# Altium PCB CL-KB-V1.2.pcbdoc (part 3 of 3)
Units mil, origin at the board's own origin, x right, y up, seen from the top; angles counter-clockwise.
Board outline 3269.95 x 5989.25 mil, 2 copper layers (Top Layer, Bottom Layer); 76 components, 86 nets, 398 pads, 855 vias.
Unrouted connection lines stored in the file: 1.
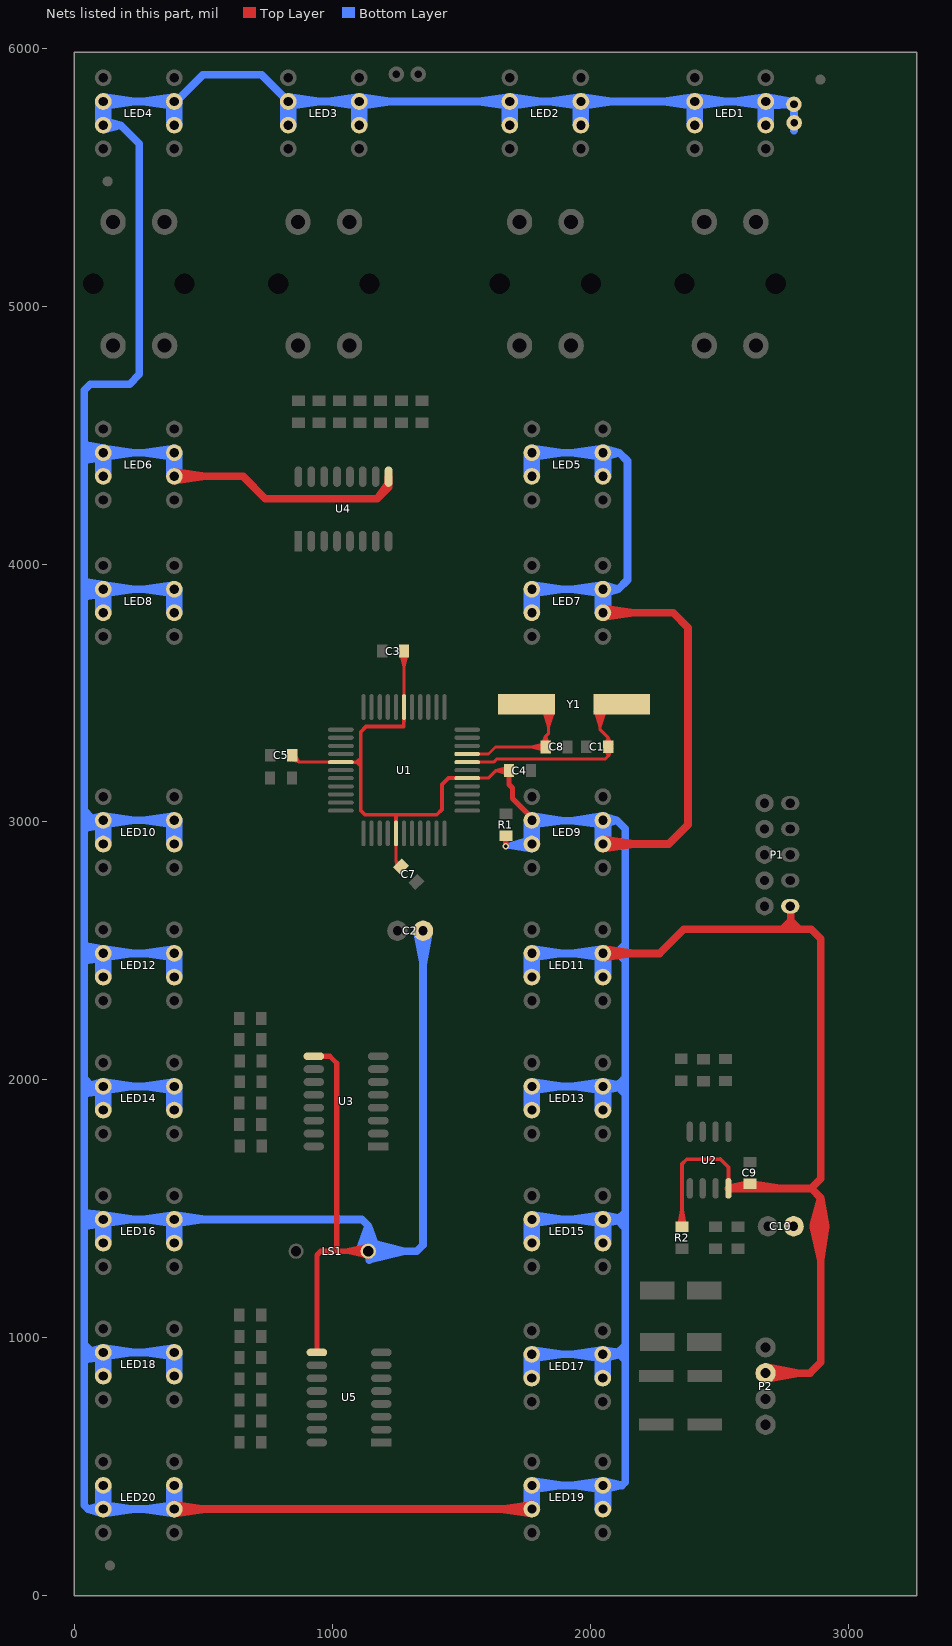
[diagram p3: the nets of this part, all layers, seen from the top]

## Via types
v1: diameter 25, hole 15, Top Layer to Bottom Layer, tented both sides, 855 vias

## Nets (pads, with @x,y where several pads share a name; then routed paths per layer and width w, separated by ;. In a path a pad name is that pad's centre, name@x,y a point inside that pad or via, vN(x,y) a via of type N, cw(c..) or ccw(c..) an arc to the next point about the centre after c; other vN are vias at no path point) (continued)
VCC: C2.1 C3.2 C4.2 C5.1 C7.2 C9.1 C10.1 LED1.A LED2.A LED3.A LED4.A LED5.A LED6.A LED7.A LED8.A LED9.A LED10.A LED11.A LED12.A LED13.A LED14.A LED15.A LED16.A LED17.A LED18.A LED19.A LED20.A LS1.1 P1.2 P2.2 pad.3 pad.4 R1.2 R2.1 U1.5 U1.17 U1.27 U1.38 U2.8 U3.9 U4.9 U5.9 | length 103418.5
  Top Layer w12: C5.1@836.52,3241.59 870,3232 ; C5.1@843,3254 870,3232 ; C5.1@843,3259 870,3232 ; C5.1@853.84,3262.85 870,3232 ; 946,3232 U1.27@990,3232 ; U1.27@1032,3232 870,3232 ; 1246,2870 U1.38@1246,2914 ; U1.38@1246,2956 1246,2846 ; C7.2@1252.81,2820.08 1246,2846 ; C3.2@1263.11,3656.25 1277,3602 ; C7.2@1271.92,2839.19 1246,2846 ; U1.17@1277,3446 C3.2@1277,3663 ; U1.17@1277,3488 1277,3532 ; C3.2@1277,3658 1277,3602 ; C3.2@1290.89,3656.25 1277,3602 ; U1.5@1522,3170 1603.68,3170 ; U1.5@1564,3170 1603.68,3170 ; C4.2@1682.61,3185.13 1632.68,3199 ; C4.2@1682.61,3212.87 1632.68,3199 ; 1246,2846 C7.2@1264.95,2827.05 1246,2846 ; 1603.68,3170 1632.68,3199 ; 1632.68,3199 C4.2@1684.5,3199 1632.68,3199
  Top Layer w15: U1.27@1032,3232 1108,3232 U1.27@1074,3232 ; 1094,3232 1103,3241 ; 1095,3232 1104,3223 ; U1.38@1246,2956 1246,3028 ; U1.38@1246,2998 1246,3028 ; U1.17@1276,3413 1276,3370 ; U1.17@1277,3404 1276,3370 ; U1.5@1480,3170 1449,3170 ; U1.5@1522,3170 1449,3170 ; R2.1@2343.56,1430.2 2356,1494 R2.1@2368.44,1430.2 ; R2.1@2356,1429 2356,1673 2374,1691 2505,1691 ; 2504,1692 2536,1660 ; U2.8@2536,1578 2536,1660 ; U2.8@2536,1606 2536,1660 ; 1246,3028 1404,3028 1424,3048 1424,3145 1449,3170 ; 1246,3028 1126,3028 1109,3045 1109,3349 1130,3370 1276,3370
  Top Layer w20: U3.9@927,2091 989,2091 ; U5.9@938.98,941.73 938.98,1320.02 953.28,1334.33 LS1.1@1138.26,1334.33 1048.73,1334.33 ; U3.9@952,2091 989,2091 ; 1016,1334.33 1016,2064 989,2091 ; LS1.1@1136.13,1314.92 1048.73,1334.33 ; LS1.1@1136.13,1353.74 1048.73,1334.33 ; C4.2@1684.5,3194 1684.5,3145.27 ; C4.2@1684.5,3199 1684.5,3145.27 ; LED9.A@1773.2,3006.17 1773.2,3015.8 1698,3091 1698,3131.77 1684.5,3145.27 ; v1(1672,2906) R1.2@1672,2947 v1(1672,2906)
  Top Layer w30: LED20.A@385.8,333.6 LED19.A@1773.2,333.6 1650.7,333.6 ; LED6.A@385.8,4341.08 651.92,4341.08 739,4254 1172,4254 ; LED20.A@387.05,316.14 508.3,333.6 LED20.A@387.05,351.05 ; LED6.A@387.05,4323.62 508.3,4341.08 LED6.A@387.05,4358.53 ; U4.9@1217,4340 1217,4299 ; LED19.A@1771.95,316.14 1650.7,333.6 ; LED19.A@1771.95,351.05 1650.7,333.6 ; LED11.A@2048.79,2490.03 2269.03,2490.03 2363,2584 2745,2584 ; LED9.A@2048.79,2914.3 2304.3,2914.3 2379,2989 2379,3754 2321.45,3811.55 LED7.A@2048.79,3811.55 ; LED11.A@2050.04,2472.57 2171.29,2490.03 LED11.A@2050.04,2507.48 ; LED9.A@2050.04,2896.85 2171.29,2914.3 LED9.A@2050.04,2931.76 ; LED7.A@2050.04,3794.09 2171.29,3811.55 LED7.A@2050.04,3829 ; C9.1@2614,1595.5 U2.8@2536,1578 2857,1578 ; C9.1@2624,1595.5 2738.5,1578 ; P2.2@2680,861 2852,861 2894,903 2894,1541 ; P2.2@2682.3,836.74 2809.37,861 P2.2@2682.3,885.26 ; 2822,2584 2811,2584 ; 2864.84,1427.78 2894,1301.36 ; 2864.93,1434.79 2894,1541 ; 2913.33,1429.65 2894,1301.36 ; 2913.32,1432.59 2894,1541 ; 1172,4254 1217,4299 ; 1172,4254 U4.9@1217,4315 ; 1217,4299 U4.9@1217,4315 ; 1217,4299 U4.9@1217,4315 ; 2745,2584 2778,2617 ; 2745,2584 2778,2584 ; 2778,2584 2778,2617 ; 2778,2584 2811,2584 ; 2778,2617 2778,2671 P1.2@2776,2673 2778,2617 ; 2778,2617 2811,2584 ; 2811,2584 2857,2584 2894,2547 2894,1615 2857,1578 ; 2857,1578 2894,1541 ; 2894,1301.36 2889,1431 2894,1541
  Bottom Layer w20: 1742.42,2927.37 v1(1672,2906) ; 1744.09,2896.17 v1(1672,2906) ; LED9.A@1744.36,2911.73 v1(1672,2906) ; LED9.A@1768.52,2936.31 v1@1680.05,2906 ; LED9.A@1772.48,2891.82 v1@1680.05,2906 ; v1(1672,2906) 1764.89,2906 LED9.A@1773.2,2914.3 v1@1680.05,2906
  Bottom Layer w30: 37,2004 61,1979 ; 37,3043 61,3018 ; 38,971 62,946 ; LED20.A@92.78,331.93 LED20.A@92.78,423.79 ; LED18.A@92.78,848.07 LED18.A@92.78,939.93 ; LED16.A@92.78,1364.21 LED16.A@92.78,1456.08 ; LED14.A@92.78,1880.35 LED14.A@92.78,1972.22 ; LED12.A@92.78,2396.5 LED12.A@92.78,2488.36 ; LED10.A@92.78,2912.64 LED10.A@92.78,3004.5 ; LED8.A@92.78,3809.88 LED8.A@92.78,3901.74 ; LED6.A@92.78,4339.41 LED6.A@92.78,4431.27 ; LED4.A@92.78,5702.4 LED4.A@92.78,5794.26 ; LED20.A@93.42,338.54 LED20.A@127.62,423.79 ; LED18.A@93.42,854.68 LED18.A@127.62,939.93 ; LED16.A@93.42,1370.82 LED16.A@127.62,1456.08 ; LED14.A@93.42,1886.96 LED14.A@127.62,1972.22 ; LED12.A@93.42,2403.1 LED12.A@127.62,2488.36 ; LED10.A@93.42,2919.24 LED10.A@127.62,3004.5 ; LED8.A@93.42,3816.49 LED8.A@127.62,3901.74 ; LED6.A@93.42,4346.02 LED6.A@127.62,4431.27 ; LED4.A@93.42,5709.01 LED4.A@127.62,5794.26 ; LED6.A@101.31,4417.86 42,4463 ; LED12.A@101.43,2474.88 41,2520 ; LED6.A@101.51,4448.13 42,4404 ; LED10.A@101.6,3021.4 39,2976 ; LED12.A@101.68,2505.31 42,2462 ; LED8.A@101.66,3888.14 43,3931 ; LED14.A@101.82,1989.25 39,1945 ; LED8.A@102,3918.87 38,3875 ; LED18.A@102.05,957.09 39,914 ; LED16.A@102.11,1442.23 41,1484 ; LED16.A@102.11,1473.26 40,1431 ; LED10.A@104.67,3022.77 64,3000 ; LED6.A@104.76,4449.57 67,4428 ; LED6.A@104.83,4416.28 66,4438 ; LED12.A@104.98,2473.32 65,2495 ; LED14.A@105.12,1990.63 64,1969 ; LED12.A@105.1,2506.76 67,2486 ; LED8.A@105.39,3920.24 63,3899 ; LED18.A@105.57,958.48 64,938 ; LED8.A@105.65,3886.51 67,3906 ; LED16.A@105.79,1474.68 65,1455 ; LED16.A@106.34,1440.67 65,1459 ; LED16.A@107.3,1475 65,1459 ; LED6.A@107.38,4415.67 56.06,4432.94 ; LED6.A@107.38,4450.21 56.06,4432.94 ; LED20.A@107.62,316.29 50.9,333.6 ; LED20.A@107.62,350.9 50.9,333.6 ; LED8.A@107.7,3920.73 67,3906 ; LED18.A@107.8,924.27 46.6,941.6 ; LED18.A@107.8,958.93 46.6,941.6 ; LED16.A@107.87,1440.4 65,1455 ; LED14.A@107.86,1956.54 44.88,1973.88 ; LED14.A@107.86,1991.23 44.88,1973.88 ; LED12.A@107.96,2472.67 42.03,2490.03 ; LED12.A@107.96,2507.38 42.03,2490.03 ; LED10.A@108.09,2988.8 37.83,3006.17 ; LED10.A@108.09,3023.54 37.83,3006.17 ; LED8.A@108.07,3886.04 38.41,3903.41 ; LED8.A@108.07,3920.78 38.41,3903.41 ; LED16.A@108.13,1440.37 36.26,1457.74 ; LED16.A@108.13,1475.12 36.26,1457.74 ; LED18.A@108.25,924.21 64,938 ; LED12.A@108.28,2472.63 67,2486 ; LED8.A@108.59,3885.99 63,3899 ; LED6.A@108.65,4415.51 67,4428 ; LED14.A@108.73,1956.45 64,1969 ; LED12.A@108.74,2507.46 65,2495 ; LED6.A@108.74,4450.38 66,4438 ; LED10.A@109.22,2988.69 64,3000 ; LED20.A@111.45,316.14 232.7,333.6 LED20.A@111.45,351.05 ; LED18.A@111.45,924.15 232.7,941.6 LED18.A@111.45,959.06 ; LED16.A@111.45,1440.29 232.7,1457.74 LED16.A@111.45,1475.2 ; LED14.A@111.45,1956.43 232.7,1973.88 LED14.A@111.45,1991.34 ; LED12.A@111.45,2472.57 232.7,2490.03 LED12.A@111.45,2507.48 ; LED10.A@111.45,2988.71 232.7,3006.17 LED10.A@111.45,3023.62 ; LED8.A@111.45,3885.96 232.7,3903.41 LED8.A@111.45,3920.87 ; LED6.A@111.45,4415.48 232.7,4432.94 LED6.A@111.45,4450.39 ; LED4.A@111.45,5778.48 232.7,5795.93 LED4.A@111.45,5813.39 ; LED4.A@112.46,5686.71 177.93,5704.07 ; LED4.A@112.46,5721.42 177.93,5704.07 ; LED16.A@114.43,1474.72 41,1484 ; LED16.A@114.49,1440.77 40,1431 ; LED18.A@114.62,924.67 39,914 ; LED8.A@114.73,3886.51 38,3875 ; LED12.A@114.89,2473.16 42,2462 ; LED8.A@114.85,3920.28 43,3931 ; LED14.A@114.89,1957.02 39,1945 ; LED6.A@115.09,4416.13 42,4404 ; LED10.A@115.16,2989.38 39,2976 ; LED12.A@115.25,2506.78 41,2520 ; LED6.A@115.33,4449.67 42,4463 ; LED20.A@126.99,338.54 LED20.A@92.78,423.79 ; LED18.A@126.99,854.68 LED18.A@92.78,939.93 ; LED16.A@126.99,1370.82 LED16.A@92.78,1456.08 ; LED14.A@126.99,1886.96 LED14.A@92.78,1972.22 ; LED12.A@126.99,2403.1 LED12.A@92.78,2488.36 ; LED10.A@126.99,2919.24 LED10.A@92.78,3004.5 ; LED8.A@126.99,3816.49 LED8.A@92.78,3901.74 ; LED6.A@126.99,4346.02 LED6.A@92.78,4431.27 ; LED4.A@126.99,5709.01 LED4.A@92.78,5794.26 ; LED20.A@127.62,331.93 LED20.A@127.62,423.79 ; LED18.A@127.62,848.07 LED18.A@127.62,939.93 ; LED16.A@127.62,1364.21 LED16.A@127.62,1456.08 ; LED14.A@127.62,1880.35 LED14.A@127.62,1972.22 ; LED12.A@127.62,2396.5 LED12.A@127.62,2488.36 ; LED10.A@127.62,2912.64 LED10.A@127.62,3004.5 ; LED8.A@127.62,3809.88 LED8.A@127.62,3901.74 ; LED6.A@127.62,4339.41 LED6.A@127.62,4431.27 ; LED4.A@127.62,5702.4 LED4.A@127.62,5794.26 ; LED20.A@368.38,423.79 LED20.A@385.8,333.6 ; LED20.A@368.38,427.13 LED20.A@368.38,335.26 ; LED18.A@368.38,939.93 LED18.A@385.8,849.74 ; LED18.A@368.38,943.27 LED18.A@368.38,851.4 ; LED16.A@368.38,1456.08 LED16.A@385.8,1365.88 ; LED16.A@368.38,1459.41 LED16.A@368.38,1367.55 ; LED14.A@368.38,1972.22 LED14.A@385.8,1882.02 ; LED14.A@368.38,1975.55 LED14.A@368.38,1883.69 ; LED12.A@368.38,2488.36 LED12.A@385.8,2398.16 ; LED12.A@368.38,2491.69 LED12.A@368.38,2399.83 ; LED10.A@368.38,3004.5 LED10.A@385.8,2914.3 ; LED10.A@368.38,3007.83 LED10.A@368.38,2915.97 ; LED8.A@368.38,3901.74 LED8.A@385.8,3811.55 ; LED8.A@368.38,3905.08 LED8.A@368.38,3813.22 ; LED6.A@368.38,4431.27 LED6.A@385.8,4341.08 ; LED6.A@368.38,4434.61 LED6.A@368.38,4342.74 ; LED4.A@368.38,5794.26 LED4.A@385.8,5704.07 ; LED4.A@368.38,5797.6 LED4.A@368.38,5705.73 ; LED20.A@369.01,420.52 LED20.A@403.22,335.26 ; LED18.A@369.01,936.66 LED18.A@403.22,851.4 ; LED16.A@369.01,1452.8 LED16.A@403.22,1367.55 ; LED14.A@369.01,1968.94 LED14.A@403.22,1883.69 ; LED12.A@369.01,2485.09 LED12.A@403.22,2399.83 ; LED10.A@369.01,3001.23 LED10.A@403.22,2915.97 ; LED8.A@369.01,3898.47 LED8.A@403.22,3813.22 ; LED6.A@369.01,4428 LED6.A@403.22,4342.74 ; LED4.A@369.01,5790.99 LED4.A@403.22,5705.73 ; LED20.A@384.55,316.14 263.3,333.6 ; LED20.A@384.55,351.05 263.3,333.6 ; LED18.A@384.55,924.15 263.3,941.6 ; LED18.A@384.55,959.06 263.3,941.6 ; LED16.A@384.55,1440.29 263.3,1457.74 ; LED16.A@384.55,1475.2 263.3,1457.74 ; LED14.A@384.55,1956.43 263.3,1973.88 ; LED14.A@384.55,1991.34 263.3,1973.88 ; LED12.A@384.55,2472.57 263.3,2490.03 ; LED12.A@384.55,2507.48 263.3,2490.03 ; LED10.A@384.55,2988.71 263.3,3006.17 ; LED10.A@384.55,3023.62 263.3,3006.17 ; LED8.A@384.55,3885.96 263.3,3903.41 ; LED8.A@384.55,3920.87 263.3,3903.41 ; LED6.A@384.55,4415.48 263.3,4432.94 ; LED6.A@384.55,4450.39 263.3,4432.94 ; LED4.A@384.55,5778.48 263.3,5795.93 ; LED4.A@384.55,5813.39 263.3,5795.93 ; LED16.A@387.05,1440.29 508.3,1457.74 LED16.A@387.05,1475.2 ; LED20.A@402.58,420.52 LED20.A@368.38,335.26 ; LED18.A@402.58,936.66 LED18.A@368.38,851.4 ; LED16.A@402.58,1452.8 LED16.A@368.38,1367.55 ; LED14.A@402.58,1968.94 LED14.A@368.38,1883.69 ; LED12.A@402.58,2485.09 LED12.A@368.38,2399.83 ; LED10.A@402.58,3001.23 LED10.A@368.38,2915.97 ; LED8.A@402.58,3898.47 LED8.A@368.38,3813.22 ; LED6.A@402.58,4428 LED6.A@368.38,4342.74 ; LED4.A@402.58,5790.99 LED4.A@368.38,5705.73 ; LED20.A@403.22,423.79 LED20.A@385.8,333.6 ; LED20.A@403.22,427.13 LED20.A@403.22,335.26 ; LED18.A@403.22,939.93 LED18.A@385.8,849.74 ; LED18.A@403.22,943.27 LED18.A@403.22,851.4 ; LED16.A@403.22,1456.08 LED16.A@385.8,1365.88 ; LED16.A@403.22,1459.41 LED16.A@403.22,1367.55 ; LED14.A@403.22,1972.22 LED14.A@385.8,1882.02 ; LED14.A@403.22,1975.55 LED14.A@403.22,1883.69 ; LED12.A@403.22,2488.36 LED12.A@385.8,2398.16 ; LED12.A@403.22,2491.69 LED12.A@403.22,2399.83 ; LED10.A@403.22,3004.5 LED10.A@385.8,2914.3 ; LED10.A@403.22,3007.83 LED10.A@403.22,2915.97 ; LED8.A@403.22,3901.74 LED8.A@385.8,3811.55 ; LED8.A@403.22,3905.08 LED8.A@403.22,3813.22 ; LED6.A@403.22,4431.27 LED6.A@385.8,4341.08 ; LED6.A@403.22,4434.61 LED6.A@403.22,4342.74 ; LED4.A@403.22,5794.26 LED4.A@385.8,5704.07 ; LED4.A@403.22,5797.6 LED4.A@403.22,5705.73 ; LED3.A@810.5,5702.4 LED3.A@810.5,5794.26 ; LED3.A@811.13,5709.01 LED3.A@845.34,5794.26 ; LED3.A@829.17,5778.48 950.42,5795.93 LED3.A@829.17,5813.39 ; LED3.A@844.71,5709.01 LED3.A@810.5,5794.26 ; LED3.A@845.34,5702.4 LED3.A@845.34,5794.26 ; LED3.A@1086.09,5794.26 LED3.A@1103.51,5704.07 ; LED3.A@1086.09,5797.6 LED3.A@1086.09,5705.73 ; LED3.A@1086.72,5790.99 LED3.A@1120.93,5705.73 ; LED3.A@1102.26,5778.48 981.01,5795.93 LED3.A@1102.26,5813.39 ; LS1.1@1104.57,1340.28 1138.26,1432.74 ; LED3.A@1104.76,5778.48 1226.01,5795.93 LED3.A@1104.76,5813.39 ; LED3.A@1120.3,5790.99 LED3.A@1086.09,5705.73 ; LED3.A@1120.93,5794.26 LED3.A@1103.51,5704.07 ; LED3.A@1120.93,5797.6 LED3.A@1120.93,5705.73 ; LS1.1@1142.46,1300.38 1277.47,1334.33 LS1.1@1142.46,1368.28 ; LS1.1@1171.95,1340.28 1138.26,1432.74 ; C2.1@1326.74,2575.7 1351,2448.63 ; C2.1@1375.26,2575.7 1351,2448.63 ; LED2.A@1670.34,5702.4 LED2.A@1670.34,5794.26 ; LED2.A@1670.97,5709.01 LED2.A@1705.18,5794.26 ; LED2.A@1686.51,5778.48 1565.26,5795.93 LED2.A@1686.51,5813.39 ; LED2.A@1689.01,5778.48 1810.26,5795.93 LED2.A@1689.01,5813.39 ; LED2.A@1704.55,5709.01 LED2.A@1670.34,5794.26 ; LED2.A@1705.18,5702.4 LED2.A@1705.18,5794.26 ; LED17.A@1754.78,932.26 LED17.A@1772.2,842.07 ; LED17.A@1754.78,935.6 LED17.A@1754.78,843.73 ; LED17.A@1755.42,928.99 LED17.A@1789.62,843.73 ; LED19.A@1755.78,423.79 LED19.A@1773.2,333.6 ; LED19.A@1755.78,427.13 LED19.A@1755.78,335.26 ; LED15.A@1755.78,1456.08 LED15.A@1773.2,1365.88 ; LED15.A@1755.78,1459.41 LED15.A@1755.78,1367.55 ; LED13.A@1755.78,1972.22 LED13.A@1773.2,1882.02 ; LED13.A@1755.78,1975.55 LED13.A@1755.78,1883.69 ; LED11.A@1755.78,2488.36 LED11.A@1773.2,2398.16 ; LED11.A@1755.78,2491.69 LED11.A@1755.78,2399.83 ; LED9.A@1755.78,3004.5 LED9.A@1773.2,2914.3 ; LED9.A@1755.78,3007.83 LED9.A@1755.76,2915.76 ; LED7.A@1755.78,3901.74 LED7.A@1773.2,3811.55 ; LED7.A@1755.78,3905.08 LED7.A@1755.78,3813.22 ; LED5.A@1755.78,4431.27 LED5.A@1773.2,4341.08 ; LED5.A@1755.78,4434.61 LED5.A@1755.78,4342.74 ; LED9.A@1755.8,3004.31 LED9.A@1772,2935 ; LED19.A@1756.41,420.52 LED19.A@1790.62,335.26 ; LED15.A@1756.41,1452.8 LED15.A@1790.62,1367.55 ; LED13.A@1756.41,1968.94 LED13.A@1790.62,1883.69 ; LED11.A@1756.41,2485.09 LED11.A@1790.62,2399.83 ; LED9.A@1756.41,3001.22 LED9.A@1790.59,2916.22 ; LED7.A@1756.41,3898.47 LED7.A@1790.62,3813.22 ; LED5.A@1756.41,4428 LED5.A@1790.62,4342.74 ; LED17.A@1773.45,916.48 1894.7,933.93 LED17.A@1773.45,951.39 ; LED9.A@1774.28,2988.7 1895.71,3004.97 ; LED19.A@1774.45,408 1895.7,425.46 LED19.A@1774.45,442.91 ; LED15.A@1774.45,1440.29 1895.7,1457.74 LED15.A@1774.45,1475.2 ; LED13.A@1774.45,1956.43 1895.7,1973.88 LED13.A@1774.45,1991.34 ; LED11.A@1774.45,2472.57 1895.7,2490.03 LED11.A@1774.45,2507.48 ; LED7.A@1774.45,3885.96 1895.7,3903.41 LED7.A@1774.45,3920.87 ; LED5.A@1774.45,4415.48 1895.7,4432.94 LED5.A@1774.45,4450.39 ; LED9.A@1774.62,3023.61 1895.71,3004.97 ; LED17.A@1788.99,928.99 LED17.A@1754.78,843.73 ; LED17.A@1789.62,932.26 LED17.A@1772.2,842.07 ; LED17.A@1789.62,935.6 LED17.A@1789.62,843.73 ; LED19.A@1789.98,420.52 LED19.A@1755.78,335.26 ; LED15.A@1789.98,1452.8 LED15.A@1755.78,1367.55 ; LED13.A@1789.98,1968.94 LED13.A@1755.78,1883.69 ; LED11.A@1789.98,2485.09 LED11.A@1755.78,2399.83 ; LED9.A@1789.99,3001.23 LED9.A@1755.76,2915.76 ; LED7.A@1789.98,3898.47 LED7.A@1755.78,3813.22 ; LED5.A@1789.98,4428 LED5.A@1755.78,4342.74 ; LED9.A@1790.52,3003.72 LED9.A@1772,2935 ; LED19.A@1790.62,423.79 LED19.A@1773.2,333.6 ; LED19.A@1790.62,427.13 LED19.A@1790.62,335.26 ; LED15.A@1790.62,1456.08 LED15.A@1773.2,1365.88 ; LED15.A@1790.62,1459.41 LED15.A@1790.62,1367.55 ; LED13.A@1790.62,1972.22 LED13.A@1773.2,1882.02 ; LED13.A@1790.62,1975.55 LED13.A@1790.62,1883.69 ; LED11.A@1790.62,2488.36 LED11.A@1773.2,2398.16 ; LED11.A@1790.62,2491.69 LED11.A@1790.62,2399.83 ; LED9.A@1790.62,3004.5 LED9.A@1773.2,2914.3 ; LED9.A@1790.62,3007.83 LED9.A@1790.59,2916.22 ; LED7.A@1790.62,3901.74 LED7.A@1773.2,3811.55 ; LED7.A@1790.62,3905.08 LED7.A@1790.62,3813.22 ; LED5.A@1790.62,4431.27 LED5.A@1773.2,4341.08 ; LED5.A@1790.62,4434.61 LED5.A@1790.62,4342.74 ; LED2.A@1945.93,5794.26 LED2.A@1963.35,5704.07 ; LED2.A@1945.92,5794.38 LED2.A@1963.35,5697.35 ; LED2.A@1945.93,5797.6 LED2.A@1945.93,5705.73 ; LED2.A@1946.57,5790.99 LED2.A@1980.78,5705.73 ; LED2.A@1962.1,5778.48 1840.85,5795.93 LED2.A@1962.1,5813.39 ; LED2.A@1964.6,5778.48 2085.85,5795.93 LED2.A@1964.6,5813.39 ; LED2.A@1980.14,5790.99 LED2.A@1945.93,5705.73 ; LED2.A@1980.78,5794.26 LED2.A@1963.35,5704.07 ; LED2.A@1980.79,5794.38 LED2.A@1963.35,5697.35 ; LED2.A@1980.78,5797.6 LED2.A@1980.78,5705.73 ; LED17.A@2030.38,840.4 LED17.A@2030.38,932.26 ; LED17.A@2031.01,847.01 LED17.A@2065.22,932.26 ; LED19.A@2031.37,331.93 LED19.A@2031.37,423.79 ; LED15.A@2031.37,1364.21 LED15.A@2031.37,1456.08 ; LED13.A@2031.37,1880.35 LED13.A@2031.37,1972.22 ; LED11.A@2031.37,2396.5 LED11.A@2031.37,2488.36 ; LED9.A@2031.37,2912.64 LED9.A@2031.37,3004.5 ; LED7.A@2031.37,3809.88 LED7.A@2031.37,3901.74 ; LED5.A@2031.37,4339.41 LED5.A@2031.37,4431.27 ; LED19.A@2032,338.54 LED19.A@2066.21,423.79 ; LED15.A@2032,1370.82 LED15.A@2066.21,1456.08 ; LED13.A@2032,1886.96 LED13.A@2066.21,1972.22 ; LED11.A@2032,2403.1 LED11.A@2066.21,2488.36 ; LED9.A@2032,2919.24 LED9.A@2066.21,3004.5 ; LED7.A@2032,3816.49 LED7.A@2066.21,3901.74 ; LED5.A@2032,4346.02 LED5.A@2066.21,4431.27 ; LED17.A@2046.55,916.48 1925.3,933.93 ; LED17.A@2046.55,951.39 1925.3,933.93 ; LED9.A@2047.37,3023.61 1926.27,3004.97 ; LED19.A@2047.54,408 1926.29,425.46 ; LED19.A@2047.54,442.91 1926.29,425.46 ; LED15.A@2047.54,1440.29 1926.29,1457.74 ; LED15.A@2047.54,1475.2 1926.29,1457.74 ; LED13.A@2047.54,1956.43 1926.29,1973.88 ; LED13.A@2047.54,1991.34 1926.29,1973.88 ; LED11.A@2047.54,2472.57 1926.29,2490.03 ; LED11.A@2047.54,2507.48 1926.29,2490.03 ; LED7.A@2047.54,3885.96 1926.29,3903.41 ; LED7.A@2047.54,3920.87 1926.29,3903.41 ; LED5.A@2047.54,4415.48 1926.29,4432.94 ; LED5.A@2047.54,4450.39 1926.29,4432.94 ; LED9.A@2047.59,3004.97 LED9.A@1772,3004.97 ; LED9.A@2047.71,2988.7 1926.27,3004.97 ; LED17.A@2048.57,951.41 2131,939 ; LED15.A@2050.51,1475.16 2135,1458 ; LED13.A@2050.54,1991.3 2135,1974 ; LED13.A@2050.59,1956.48 2135,1974 ; LED15.A@2050.62,1440.34 2135,1458 ; LED11.A@2050.63,2472.62 2131.97,2490.03 ; LED11.A@2050.63,2507.43 2131.97,2490.03 ; LED17.A@2050.69,916.67 2131,939 ; LED19.A@2050.86,408.08 2122.54,425.46 ; LED19.A@2050.86,442.84 2122.54,425.46 ; LED5.A@2051.21,4415.61 2111.94,4432.94 ; LED5.A@2051.21,4450.27 2111.94,4432.94 ; LED7.A@2051.36,3886.1 2108.41,3903.41 ; LED7.A@2051.36,3920.72 2108.41,3903.41 ; LED9.A@2051.62,2988.9 2102.83,3006.17 ; LED9.A@2051.62,3023.44 2102.83,3006.17 ; LED17.A@2064.58,847.01 LED17.A@2030.38,932.26 ; LED17.A@2065.22,840.4 LED17.A@2065.22,932.26 ; LED19.A@2065.58,338.54 LED19.A@2031.37,423.79 ; LED15.A@2065.58,1370.82 LED15.A@2031.37,1456.08 ; LED13.A@2065.58,1886.96 LED13.A@2031.37,1972.22 ; LED11.A@2065.58,2403.1 LED11.A@2031.37,2488.36 ; LED9.A@2065.58,2919.24 LED9.A@2031.37,3004.5 ; LED7.A@2065.58,3816.49 LED7.A@2031.37,3901.74 ; LED5.A@2065.58,4346.02 LED5.A@2031.37,4431.27 ; LED19.A@2066.21,331.93 LED19.A@2066.21,423.79 ; LED15.A@2066.21,1364.21 LED15.A@2066.21,1456.08 ; LED13.A@2066.21,1880.35 LED13.A@2066.21,1972.22 ; LED11.A@2066.21,2396.5 LED11.A@2066.21,2488.36 ; LED9.A@2066.21,2912.64 LED9.A@2066.21,3004.5 ; LED7.A@2066.21,3809.88 LED7.A@2066.21,3901.74 ; LED5.A@2066.21,4339.41 LED5.A@2066.21,4431.27 ; 2103,2493.03 2128,2517.03 ; 2104,1977 2129,2001 ; 2105,939 2130,963 ; 2106,1974 2130,1949 ; 2106,2493.03 2130,2468.03 ; 2107,939 2132,915 ; 2108,1453 2132,1428 ; 2110,1461 2135,1485 ; 2135,935 2131,939 ; LED1.A@2388.06,5794.26 LED1.A@2405.48,5704.07 ; LED1.A@2388.06,5797.6 LED1.A@2388.06,5705.73 ; LED1.A@2388.69,5790.99 LED1.A@2422.9,5705.73 ; LED1.A@2404.23,5778.48 2282.98,5795.93 LED1.A@2404.23,5813.39 ; LED1.A@2406.73,5778.48 2527.98,5795.93 LED1.A@2406.73,5813.39 ; LED1.A@2422.27,5790.99 LED1.A@2388.06,5705.73 ; LED1.A@2422.9,5794.26 LED1.A@2405.48,5704.07 ; LED1.A@2422.9,5797.6 LED1.A@2422.9,5705.73 ; LED1.A@2663.65,5702.4 LED1.A@2663.65,5794.26 ; LED1.A@2664.28,5709.01 LED1.A@2698.49,5794.26 ; LED1.A@2679.82,5778.48 2558.57,5795.93 LED1.A@2679.82,5813.39 ; LED1.A@2697.86,5709.01 LED1.A@2663.65,5794.26 ; LED1.A@2698.49,5702.4 LED1.A@2698.49,5794.26 ; 36,931 36,1965 ; 36,931 36,348.5 50.9,333.6 ; 36,931 46.6,941.6 ; 36,1965 36,2484 ; 36,1965 44.88,1973.88 ; 36,2484 36,3008 ; 36,2484 42.03,2490.03 ; 36,3008 36,3901 ; 36,3008 37.83,3006.17 ; 36,3901 36,4453 ; 36,3901 38.41,3903.41 ; 36,4453 36,4675 60,4699 212,4699 250,4737 250,5632 177.93,5704.07 ; 36,4453 56.06,4432.94 ; 36.26,1457.74 1113.26,1457.74 1138.26,1432.74 ; 36.26,1457.74 LED16.A@110.2,1457.74 ; 37.83,3006.17 LED10.A@385.8,3006.17 ; 37.83,3006.17 LED10.A@110.2,3006.17 ; 38,3875 63,3899 ; 38,3875 LED8.A@110.2,3903.41 ; 38.41,3903.41 LED8.A@385.8,3903.41 ; 38.41,3903.41 LED8.A@110.2,3903.41 ; 39,914 64,938 ; 39,914 LED18.A@110.2,941.6 ; 39,1945 64,1969 ; 39,1945 LED14.A@110.2,1973.88 ; 39,2976 64,3000 ; 39,2976 LED10.A@110.2,3006.17 ; 40,1431 65,1455 ; 40,1431 LED16.A@110.2,1457.74 ; 41,1484 65,1459 ; 41,1484 LED16.A@110.2,1457.74 ; 41,2520 65,2495 ; 41,2520 LED12.A@110.2,2490.03 ; 42,2462 67,2486 ; 42,2462 LED12.A@110.2,2490.03 ; 42.03,2490.03 LED12.A@385.8,2490.03 ; 42.03,2490.03 LED12.A@110.2,2490.03 ; 42,4404 67,4428 ; 42,4404 LED6.A@110.2,4432.94 ; 42,4463 66,4438 ; 42,4463 LED6.A@110.2,4432.94 ; 43,3931 67,3906 ; 43,3931 LED8.A@110.2,3903.41 ; 44.88,1973.88 LED14.A@385.8,1973.88 ; 44.88,1973.88 LED14.A@110.2,1973.88 ; 46.6,941.6 LED18.A@385.8,941.6 ; 46.6,941.6 LED18.A@110.2,941.6 ; 50.9,333.6 LED20.A@110.2,333.6 ; 50.9,333.6 LED20.A@110.2,333.6 ; 56.06,4432.94 LED6.A@385.8,4432.94 ; 56.06,4432.94 LED6.A@110.2,4432.94 ; 63,3899 LED8.A@110.2,3903.41 ; 64,938 LED18.A@110.2,941.6 ; 64,1969 LED14.A@110.2,1973.88 ; 64,3000 LED10.A@110.2,3006.17 ; 65,1455 LED16.A@110.2,1457.74 ; 65,1459 LED16.A@110.2,1457.74 ; 65,2495 LED12.A@110.2,2490.03 ; 66,4438 LED6.A@110.2,4432.94 ; 67,2486 LED12.A@110.2,2490.03 ; 67,3906 LED8.A@110.2,3903.41 ; 67,4428 LED6.A@110.2,4432.94 ; LED20.A@92.78,423.79 LED20.A@110.2,333.6 ; LED20.A@92.78,423.79 LED20.A@110.2,333.6 ; LED18.A@92.78,939.93 LED18.A@110.2,849.74 ; LED18.A@92.78,939.93 LED18.A@110.2,849.74 ; LED16.A@92.78,1456.08 LED16.A@110.2,1365.88 ; LED16.A@92.78,1456.08 LED16.A@110.2,1365.88 ; LED14.A@92.78,1972.22 LED14.A@110.2,1882.02 ; LED14.A@92.78,1972.22 LED14.A@110.2,1882.02 ; LED12.A@92.78,2488.36 LED12.A@110.2,2398.16 ; LED12.A@92.78,2488.36 LED12.A@110.2,2398.16 ; LED10.A@92.78,3004.5 LED10.A@110.2,2914.3 ; LED10.A@92.78,3004.5 LED10.A@110.2,2914.3 ; LED8.A@92.78,3901.74 LED8.A@110.2,3811.55 ; LED8.A@92.78,3901.74 LED8.A@110.2,3811.55 ; LED6.A@92.78,4431.27 LED6.A@110.2,4341.08 ; LED6.A@92.78,4431.27 LED6.A@110.2,4341.08 ; LED4.A@92.78,5794.26 LED4.A@110.2,5704.07 ; LED4.A@92.78,5794.26 LED4.A@110.2,5704.07 ; LED20.A@110.2,333.6 LED20.A@385.8,333.6 ; LED20.A@110.2,333.6 LED20.A@110.2,425.46 ; LED20.A@110.2,333.6 LED20.A@127.62,423.79 ; LED20.A@110.2,333.6 LED20.A@110.2,425.46 ; LED20.A@110.2,425.46 92.78,335.26 LED20.A@110.2,425.46 ; LED20.A@110.2,425.46 127.62,335.26 LED20.A@110.2,425.46 ; LED18.A@110.2,849.74 LED18.A@110.2,941.6 ; LED18.A@110.2,849.74 LED18.A@127.62,939.93 ; LED18.A@110.2,849.74 LED18.A@110.2,941.6 ; LED18.A@110.2,941.6 92.78,851.4 LED18.A@110.2,941.6 ; LED18.A@110.2,941.6 127.62,851.4 LED18.A@110.2,941.6 ; LED16.A@110.2,1365.88 LED16.A@110.2,1457.74 ; LED16.A@110.2,1365.88 LED16.A@127.62,1456.08 ; LED16.A@110.2,1365.88 LED16.A@110.2,1457.74 ; LED16.A@110.2,1457.74 92.78,1367.55 LED16.A@110.2,1457.74 ; LED16.A@110.2,1457.74 127.62,1367.55 LED16.A@110.2,1457.74 ; LED14.A@110.2,1882.02 LED14.A@110.2,1973.88 ; LED14.A@110.2,1882.02 LED14.A@127.62,1972.22 ; LED14.A@110.2,1882.02 LED14.A@110.2,1973.88 ; LED14.A@110.2,1973.88 92.78,1883.69 LED14.A@110.2,1973.88 ; LED14.A@110.2,1973.88 127.62,1883.69 LED14.A@110.2,1973.88 ; LED12.A@110.2,2398.16 LED12.A@110.2,2490.03 ; LED12.A@110.2,2398.16 LED12.A@127.62,2488.36 ; LED12.A@110.2,2398.16 LED12.A@110.2,2490.03 ; LED12.A@110.2,2490.03 92.78,2399.83 LED12.A@110.2,2490.03 ; LED12.A@110.2,2490.03 127.62,2399.83 LED12.A@110.2,2490.03 ; LED10.A@110.2,2914.3 LED10.A@110.2,3006.17 ; LED10.A@110.2,2914.3 LED10.A@127.62,3004.5 ; LED10.A@110.2,2914.3 LED10.A@110.2,3006.17 ; LED10.A@110.2,3006.17 92.78,2915.97 LED10.A@110.2,3006.17 ; LED10.A@110.2,3006.17 127.62,2915.97 LED10.A@110.2,3006.17 ; LED8.A@110.2,3811.55 LED8.A@110.2,3903.41 ; LED8.A@110.2,3811.55 LED8.A@127.62,3901.74 ; LED8.A@110.2,3811.55 LED8.A@110.2,3903.41 ; LED8.A@110.2,3903.41 92.78,3813.22 LED8.A@110.2,3903.41 ; LED8.A@110.2,3903.41 127.62,3813.22 LED8.A@110.2,3903.41 ; LED6.A@110.2,4341.08 LED6.A@110.2,4432.94 ; LED6.A@110.2,4341.08 LED6.A@127.62,4431.27 ; LED6.A@110.2,4341.08 LED6.A@110.2,4432.94 ; LED6.A@110.2,4432.94 92.78,4342.74 LED6.A@110.2,4432.94 ; LED6.A@110.2,4432.94 127.62,4342.74 LED6.A@110.2,4432.94 ; LED4.A@110.2,5704.07 177.93,5704.07 ; LED4.A@110.2,5704.07 LED4.A@110.2,5795.93 ; LED4.A@110.2,5704.07 LED4.A@127.62,5794.26 ; LED4.A@110.2,5704.07 LED4.A@110.2,5795.93 ; LED4.A@110.2,5795.93 392.93,5795.93 497,5900 723.85,5900 LED3.A@827.92,5795.93 ; LED4.A@110.2,5795.93 92.78,5705.73 LED4.A@110.2,5795.93 ; LED4.A@110.2,5795.93 127.62,5705.73 LED4.A@110.2,5795.93 ; 263.3,333.6 LED20.A@385.8,333.6 ; 263.3,941.6 LED18.A@385.8,941.6 ; 263.3,1457.74 LED16.A@385.8,1457.74 ; 263.3,1973.88 LED14.A@385.8,1973.88 ; 263.3,2490.03 LED12.A@385.8,2490.03 ; 263.3,3006.17 LED10.A@385.8,3006.17 ; 263.3,3903.41 LED8.A@385.8,3903.41 ; 263.3,4432.94 LED6.A@385.8,4432.94 ; 263.3,5795.93 LED4.A@385.8,5795.93 ; LED20.A@368.38,335.26 LED20.A@385.8,425.46 ; LED20.A@368.38,335.26 LED20.A@385.8,425.46 ; LED18.A@368.38,851.4 LED18.A@385.8,941.6 ; LED18.A@368.38,851.4 LED18.A@385.8,941.6 ; LED16.A@368.38,1367.55 LED16.A@385.8,1457.74 ; LED16.A@368.38,1367.55 LED16.A@385.8,1457.74 ; LED14.A@368.38,1883.69 LED14.A@385.8,1973.88 ; LED14.A@368.38,1883.69 LED14.A@385.8,1973.88 ; LED12.A@368.38,2399.83 LED12.A@385.8,2490.03 ; LED12.A@368.38,2399.83 LED12.A@385.8,2490.03 ; LED10.A@368.38,2915.97 LED10.A@385.8,3006.17 ; LED10.A@368.38,2915.97 LED10.A@385.8,3006.17 ; LED8.A@368.38,3813.22 LED8.A@385.8,3903.41 ; LED8.A@368.38,3813.22 LED8.A@385.8,3903.41 ; LED6.A@368.38,4342.74 LED6.A@385.8,4432.94 ; LED6.A@368.38,4342.74 LED6.A@385.8,4432.94 ; LED4.A@368.38,5705.73 LED4.A@385.8,5795.93 ; LED4.A@368.38,5705.73 LED4.A@385.8,5795.93 ; LED20.A@385.8,333.6 LED20.A@385.8,425.46 ; LED20.A@385.8,333.6 LED20.A@385.8,425.46 ; LED20.A@385.8,425.46 LED20.A@403.22,335.26 ; LED18.A@385.8,849.74 LED18.A@385.8,941.6 ; LED18.A@385.8,849.74 LED18.A@385.8,941.6 ; LED18.A@385.8,941.6 LED18.A@403.22,851.4 ; LED16.A@385.8,1365.88 LED16.A@385.8,1457.74 ; LED16.A@385.8,1365.88 LED16.A@385.8,1457.74 ; LED16.A@385.8,1457.74 LED16.A@403.22,1367.55 ; LED14.A@385.8,1882.02 LED14.A@385.8,1973.88 ; LED14.A@385.8,1882.02 LED14.A@385.8,1973.88 ; LED14.A@385.8,1973.88 LED14.A@403.22,1883.69 ; LED12.A@385.8,2398.16 LED12.A@385.8,2490.03 ; LED12.A@385.8,2398.16 LED12.A@385.8,2490.03 ; LED12.A@385.8,2490.03 LED12.A@403.22,2399.83 ; LED10.A@385.8,2914.3 LED10.A@385.8,3006.17 ; LED10.A@385.8,2914.3 LED10.A@385.8,3006.17 ; LED10.A@385.8,3006.17 LED10.A@403.22,2915.97 ; LED8.A@385.8,3811.55 LED8.A@385.8,3903.41 ; LED8.A@385.8,3811.55 LED8.A@385.8,3903.41 ; LED8.A@385.8,3903.41 LED8.A@403.22,3813.22 ; LED6.A@385.8,4341.08 LED6.A@385.8,4432.94 ; LED6.A@385.8,4341.08 LED6.A@385.8,4432.94 ; LED6.A@385.8,4432.94 LED6.A@403.22,4342.74 ; LED4.A@385.8,5704.07 LED4.A@385.8,5795.93 ; LED4.A@385.8,5704.07 LED4.A@385.8,5795.93 ; LED4.A@385.8,5795.93 LED4.A@403.22,5705.73 ; LED3.A@810.5,5794.26 LED3.A@827.92,5704.07 ; LED3.A@810.5,5794.26 LED3.A@827.92,5704.07 ; LED3.A@827.92,5704.07 LED3.A@827.92,5795.93 ; LED3.A@827.92,5704.07 LED3.A@845.34,5794.26 ; LED3.A@827.92,5704.07 LED3.A@827.92,5795.93 ; LED3.A@827.92,5795.93 LED3.A@1103.51,5795.93 ; LED3.A@827.92,5795.93 810.5,5705.73 LED3.A@827.92,5795.93 ; LED3.A@827.92,5795.93 845.34,5705.73 LED3.A@827.92,5795.93 ; LED3.A@1086.09,5705.73 LED3.A@1103.51,5795.93 ; LED3.A@1086.09,5705.73 LED3.A@1103.51,5795.93 ; LED3.A@1103.51,5704.07 LED3.A@1103.51,5795.93 ; LED3.A@1103.51,5704.07 LED3.A@1103.51,5795.93 ; LED3.A@1103.51,5795.93 LED2.A@1687.76,5795.93 ; LED3.A@1103.51,5795.93 LED3.A@1120.93,5705.73 ; 1138.26,1432.74 LS1.1@1138.26,1334.33 1326.67,1334.33 1351,1358.66 C2.1@1351,2578 1351,2448.63 ; LED2.A@1670.34,5794.26 LED2.A@1687.76,5704.07 ; LED2.A@1670.34,5794.26 LED2.A@1687.76,5704.07 ; LED2.A@1687.76,5704.07 LED2.A@1687.76,5795.93 ; LED2.A@1687.76,5704.07 LED2.A@1705.18,5794.26 ; LED2.A@1687.76,5704.07 LED2.A@1687.76,5795.93 ; LED2.A@1687.76,5795.93 LED2.A@1963.35,5795.93 ; LED2.A@1687.76,5795.93 1670.34,5705.73 LED2.A@1687.76,5795.93 ; LED2.A@1687.76,5795.93 1705.18,5705.73 LED2.A@1687.76,5795.93 ; LED17.A@1754.78,843.73 LED17.A@1772.2,933.93 ; LED17.A@1754.78,843.73 LED17.A@1772.2,933.93 ; LED19.A@1755.78,335.26 LED19.A@1773.2,425.46 ; LED19.A@1755.78,335.26 LED19.A@1773.2,425.46 ; LED15.A@1755.78,1367.55 LED15.A@1773.2,1457.74 ; LED15.A@1755.78,1367.55 LED15.A@1773.2,1457.74 ; LED13.A@1755.78,1883.69 LED13.A@1773.2,1973.88 ; LED13.A@1755.78,1883.69 LED13.A@1773.2,1973.88 ; LED11.A@1755.78,2399.83 LED11.A@1773.2,2490.03 ; LED11.A@1755.78,2399.83 LED11.A@1773.2,2490.03 ; LED9.A@1755.76,2915.76 LED9.A@1772,3004.97 ; LED9.A@1755.76,2915.76 LED9.A@1773.2,3006.17 ; LED7.A@1755.78,3813.22 LED7.A@1773.2,3903.41 ; LED7.A@1755.78,3813.22 LED7.A@1773.2,3903.41 ; LED5.A@1755.78,4342.74 LED5.A@1773.2,4432.94 ; LED5.A@1755.78,4342.74 LED5.A@1773.2,4432.94 ; LED9.A@1772,2935 LED9.A@1772,3004.97 ; LED9.A@1772,2935 LED9.A@1773.2,3006.17 ; LED9.A@1772,3004.97 LED9.A@1790.59,2916.22 ; LED9.A@1772,3004.97 LED9.A@1773.2,2914.3 ; LED17.A@1772.2,842.07 LED17.A@1772.2,933.93 ; LED17.A@1772.2,842.07 LED17.A@1772.2,933.93 ; LED17.A@1772.2,933.93 LED17.A@2047.8,933.93 ; LED17.A@1772.2,933.93 LED17.A@1789.62,843.73 ; LED19.A@1773.2,333.6 LED19.A@1773.2,425.46 ; LED19.A@1773.2,333.6 LED19.A@1773.2,425.46 ; LED19.A@1773.2,425.46 2122.54,425.46 ; LED19.A@1773.2,425.46 LED19.A@1790.62,335.26 ; LED15.A@1773.2,1365.88 LED15.A@1773.2,1457.74 ; LED15.A@1773.2,1365.88 LED15.A@1773.2,1457.74 ; LED15.A@1773.2,1457.74 LED15.A@2048.79,1457.74 ; LED15.A@1773.2,1457.74 LED15.A@1790.62,1367.55 ; LED13.A@1773.2,1882.02 LED13.A@1773.2,1973.88 ; LED13.A@1773.2,1882.02 LED13.A@1773.2,1973.88 ; LED13.A@1773.2,1973.88 LED13.A@2048.79,1973.88 ; LED13.A@1773.2,1973.88 LED13.A@1790.62,1883.69 ; LED11.A@1773.2,2398.16 LED11.A@1773.2,2490.03 ; LED11.A@1773.2,2398.16 LED11.A@1773.2,2490.03 ; LED11.A@1773.2,2490.03 2131.97,2490.03 ; LED11.A@1773.2,2490.03 LED11.A@1790.62,2399.83 ; LED9.A@1773.2,2914.3 LED9.A@1773.2,3006.17 ; LED9.A@1773.2,3006.17 LED9.A@1790.59,2916.22 ; LED9.A@1773.2,3006.17 1895.71,3004.97 ; LED7.A@1773.2,3811.55 LED7.A@1773.2,3903.41 ; LED7.A@1773.2,3811.55 LED7.A@1773.2,3903.41 ; LED7.A@1773.2,3903.41 2108.41,3903.41 ; LED7.A@1773.2,3903.41 LED7.A@1790.62,3813.22 ; LED5.A@1773.2,4341.08 LED5.A@1773.2,4432.94 ; LED5.A@1773.2,4341.08 LED5.A@1773.2,4432.94 ; LED5.A@1773.2,4432.94 2111.94,4432.94 ; LED5.A@1773.2,4432.94 LED5.A@1790.62,4342.74 ; 1925.3,933.93 LED17.A@2047.8,933.93 ; 1926.29,425.46 LED19.A@2048.79,425.46 ; 1926.29,1457.74 LED15.A@2048.79,1457.74 ; 1926.29,1973.88 LED13.A@2048.79,1973.88 ; 1926.29,2490.03 LED11.A@2048.79,2490.03 ; 1926.27,3004.97 LED9.A@2048.79,3006.17 ; 1926.29,3903.41 LED7.A@2048.79,3903.41 ; 1926.29,4432.94 LED5.A@2048.79,4432.94 ; LED2.A@1945.93,5705.73 LED2.A@1963.35,5795.93 ; LED2.A@1945.93,5705.73 LED2.A@1963.35,5795.93 ; LED2.A@1963.35,5697.35 LED2.A@1963.35,5795.93 ; LED2.A@1963.35,5697.35 LED2.A@1963.35,5795.93 ; LED2.A@1963.35,5704.07 LED2.A@1963.35,5795.93 ; LED2.A@1963.35,5704.07 LED2.A@1963.35,5795.93 ; LED2.A@1963.35,5795.93 LED1.A@2405.48,5795.93 ; LED2.A@1963.35,5795.93 LED2.A@1980.78,5705.73 ; LED17.A@2030.38,932.26 LED17.A@2047.8,842.07 ; LED17.A@2030.38,932.26 LED17.A@2047.8,842.07 ; LED19.A@2031.37,423.79 LED19.A@2048.79,333.6 ; LED19.A@2031.37,423.79 LED19.A@2048.79,333.6 ; LED15.A@2031.37,1456.08 LED15.A@2048.79,1365.88 ; LED15.A@2031.37,1456.08 LED15.A@2048.79,1365.88 ; LED13.A@2031.37,1972.22 LED13.A@2048.79,1882.02 ; LED13.A@2031.37,1972.22 LED13.A@2048.79,1882.02 ; LED11.A@2031.37,2488.36 LED11.A@2048.79,2398.16 ; LED11.A@2031.37,2488.36 LED11.A@2048.79,2398.16 ; LED9.A@2031.37,3004.5 LED9.A@2048.79,2914.3 ; LED9.A@2031.37,3004.5 LED9.A@2048.79,2914.3 ; LED7.A@2031.37,3901.74 LED7.A@2048.79,3811.55 ; LED7.A@2031.37,3901.74 LED7.A@2048.79,3811.55 ; LED5.A@2031.37,4431.27 LED5.A@2048.79,4341.08 ; LED5.A@2031.37,4431.27 LED5.A@2048.79,4341.08 ; LED17.A@2047.8,842.07 LED17.A@2047.8,933.93 ; LED17.A@2047.8,842.07 LED17.A@2065.22,932.26 ; LED17.A@2047.8,842.07 LED17.A@2047.8,933.93 ; LED17.A@2047.8,933.93 2052.86,939 2131,939 ; LED17.A@2047.8,933.93 2131,939 ; LED17.A@2047.8,933.93 2030.38,843.73 LED17.A@2047.8,933.93 ; LED17.A@2047.8,933.93 2065.22,843.73 LED17.A@2047.8,933.93 ; LED19.A@2048.79,333.6 LED19.A@2048.79,425.46 ; LED19.A@2048.79,333.6 LED19.A@2066.21,423.79 ; LED19.A@2048.79,333.6 LED19.A@2048.79,425.46 ; LED19.A@2048.79,425.46 2031.37,335.26 LED19.A@2048.79,425.46 ; LED19.A@2048.79,425.46 2066.21,335.26 LED19.A@2048.79,425.46 ; LED15.A@2048.79,1365.88 LED15.A@2048.79,1457.74 ; LED15.A@2048.79,1365.88 LED15.A@2066.21,1456.08 ; LED15.A@2048.79,1365.88 LED15.A@2048.79,1457.74 ; LED15.A@2048.79,1457.74 2049.05,1458 2135,1458 ; LED15.A@2048.79,1457.74 2135,1458 ; LED15.A@2048.79,1457.74 2031.37,1367.55 LED15.A@2048.79,1457.74 ; LED15.A@2048.79,1457.74 2066.21,1367.55 LED15.A@2048.79,1457.74 ; LED13.A@2048.79,1882.02 LED13.A@2048.79,1973.88 ; LED13.A@2048.79,1882.02 LED13.A@2066.21,1972.22 ; LED13.A@2048.79,1882.02 LED13.A@2048.79,1973.88 ; LED13.A@2048.79,1973.88 2048.9,1974 2135,1974 ; LED13.A@2048.79,1973.88 2135,1974 ; LED13.A@2048.79,1973.88 2031.37,1883.69 LED13.A@2048.79,1973.88 ; LED13.A@2048.79,1973.88 2066.21,1883.69 LED13.A@2048.79,1973.88 ; LED11.A@2048.79,2398.16 LED11.A@2048.79,2490.03 ; LED11.A@2048.79,2398.16 LED11.A@2066.21,2488.36 ; LED11.A@2048.79,2398.16 LED11.A@2048.79,2490.03 ; LED11.A@2048.79,2490.03 2031.37,2399.83 LED11.A@2048.79,2490.03 ; LED11.A@2048.79,2490.03 2066.21,2399.83 LED11.A@2048.79,2490.03 ; LED9.A@2048.79,2914.3 LED9.A@2048.79,3006.17 ; LED9.A@2048.79,2914.3 LED9.A@2066.21,3004.5 ; LED9.A@2048.79,2914.3 LED9.A@2048.79,3006.17 ; LED9.A@2048.79,3006.17 2102.83,3006.17 ; LED9.A@2048.79,3006.17 2031.37,2915.97 LED9.A@2048.79,3006.17 ; LED9.A@2048.79,3006.17 2066.21,2915.97 LED9.A@2048.79,3006.17 ; LED7.A@2048.79,3811.55 LED7.A@2048.79,3903.41 ; LED7.A@2048.79,3811.55 LED7.A@2066.21,3901.74 ; LED7.A@2048.79,3811.55 LED7.A@2048.79,3903.41 ; LED7.A@2048.79,3903.41 2031.37,3813.22 LED7.A@2048.79,3903.41 ; LED7.A@2048.79,3903.41 2066.21,3813.22 LED7.A@2048.79,3903.41 ; LED5.A@2048.79,4341.08 LED5.A@2048.79,4432.94 ; LED5.A@2048.79,4341.08 LED5.A@2066.21,4431.27 ; LED5.A@2048.79,4341.08 LED5.A@2048.79,4432.94 ; LED5.A@2048.79,4432.94 2031.37,4342.74 LED5.A@2048.79,4432.94 ; LED5.A@2048.79,4432.94 2066.21,4342.74 LED5.A@2048.79,4432.94 ; 2102.83,3006.17 2135,2974 2135,437.92 2122.54,425.46 ; 2108.41,3903.41 2144,3939 2144,4400.88 2111.94,4432.94 ; LED1.A@2388.06,5705.73 LED1.A@2405.48,5795.93 ; LED1.A@2388.06,5705.73 LED1.A@2405.48,5795.93 ; LED1.A@2405.48,5704.07 LED1.A@2405.48,5795.93 ; LED1.A@2405.48,5704.07 LED1.A@2405.48,5795.93 ; LED1.A@2405.48,5795.93 LED1.A@2681.07,5795.93 ; LED1.A@2405.48,5795.93 LED1.A@2422.9,5705.73 ; LED1.A@2663.65,5794.26 LED1.A@2681.07,5704.07 ; LED1.A@2663.65,5794.26 LED1.A@2681.07,5704.07 ; LED1.A@2681.07,5704.07 LED1.A@2681.07,5795.93 ; LED1.A@2681.07,5704.07 LED1.A@2698.49,5794.26 ; LED1.A@2681.07,5704.07 LED1.A@2681.07,5795.93 ; LED1.A@2681.07,5795.93 pad.3@2779.07,5795.93 ; LED1.A@2681.07,5795.93 2663.65,5705.73 LED1.A@2681.07,5795.93 ; LED1.A@2681.07,5795.93 2698.49,5705.73 LED1.A@2681.07,5795.93 ; LED1.A@2681.07,5795.93 pad.3@2790,5785 ; pad.3@2779.07,5795.93 pad.3@2790,5785 ; pad.3@2779.07,5795.93 2682.63,5813.36 pad.3@2790,5785 ; pad.3@2779.07,5795.93 2682.63,5778.5 pad.3@2790,5785 ; pad.3@2790,5785 2790,5683 pad.3@2790,5785 ; pad.3@2790,5785 pad.4@2791,5713 pad.3@2790,5785
XTAL1: C8.1 U1.8 Y1.1 | length 1083.9
  Top Layer w12: U1.8@1522,3264 1605,3264 ; U1.8@1564,3264 1605,3264 ; C8.1@1812.76,3298.69 1826.5,3332.5 ; Y1.1@1819.23,3428.04 1838,3370 ; C8.1@1824.75,3277.11 1770.5,3291 ; C8.1@1824.75,3304.89 1770.5,3291 ; C8.1@1826.5,3296 1826.5,3332.5 ; Y1.1@1831.01,3430.6 1838,3370 ; C8.1@1840.24,3298.69 1826.5,3332.5 ; Y1.1@1844.99,3430.6 1838,3370 ; Y1.1@1856.77,3428.04 1838,3370 ; 1605,3264 1632,3291 C8.1@1826.5,3291 ; 1770.5,3291 C8.1@1826.5,3291 ; C8.1@1826.5,3291 1826.5,3332.5 ; 1826.5,3332.5 1838,3344 1838,3431 1838,3370
XTAL2: C1.1 U1.7 Y1.2 | length 1276.5
  Top Layer w12: U1.7@1522,3232 1625,3232 1638,3245 2059,3245 2070,3256 ; U1.7@1564,3232 1608,3232 ; Y1.2@2019.23,3428.04 2038,3370 ; Y1.2@2031.01,3430.6 2038,3370 ; Y1.2@2044.99,3430.6 2038,3370 ; C1.1@2055.91,3283.62 2070,3256 ; C1.1@2055.9,3300.32 2069.5,3326.5 ; Y1.2@2056.77,3428.04 2038,3370 ; C1.1@2069.5,3287 2070,3256 ; C1.1@2069.5,3292 2069.5,3326.5 ; C1.1@2069.5,3297 2069.5,3326.5 ; C1.1@2070,3292 2070,3256 ; C1.1@2083.1,3300.32 2069.5,3326.5 ; C1.1@2083.19,3284.06 2070,3256 ; 2038,3370 2038,3431 2038,3358 2069.5,3326.5
pads on no net: Mini_S1.0 Mini_S2.0 Mini_S3.0 Mini_S4.0 P1.3 U1.12

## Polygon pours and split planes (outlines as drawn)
GND on Top Layer "GND" (solid, remove dead copper, pour order 3): 20,5800 20,5860 cw(c120,5860) 120,5960 180,5960 2700,5960 cw(c2700,5860) 2800,5860 2800,5720 2800,5700 ccw(c2880,5700) 2880,5620 cw(c2880,5560) 2940,5560 2940,5180 2940,480 cw(c2840,480) 2840,380 2720,380 2560,380 ccw(c2560,280) 2460,280 2460,80 cw(c2400,80) 2400,20 2180,20 880,20 cw(c880,80) 820,80 820,160 820,240 ccw(c760,240) 760,300 520,300 ccw(c520,240) 460,240 460,120 cw(c360,120) 360,20 140,20 120,20 cw(c120,120) 20,120 20,380
GND on Bottom Layer "GND" (solid, remove dead copper, pour order 4): 20,5800 20,5860 cw(c120,5860) 120,5960 180,5960 2700,5960 cw(c2700,5860) 2800,5860 2800,5720 2800,5700 ccw(c2880,5700) 2880,5620 cw(c2880,5560) 2940,5560 2940,5180 2940,480 cw(c2840,480) 2840,380 2720,380 2560,380 ccw(c2560,280) 2460,280 2460,80 cw(c2400,80) 2400,20 2180,20 880,20 cw(c880,80) 820,80 820,160 820,240 ccw(c760,240) 760,300 520,300 ccw(c520,240) 460,240 460,120 cw(c360,120) 360,20 140,20 120,20 cw(c120,120) 20,120 20,380

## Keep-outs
Keep-Out Layer:
  circle w10: c590.55,4724.41 r78.74
  circle w10: c2808.66,5439.01 r78.74
  circle w10: c2811.05,144.1 r78.74
  circle w10: c2165.35,4724.41 r78.74
  circle w10: c600.42,5713.98 r78.74
  circle w10: c604.33,3005.91 r78.74
  circle w10: c604.33,149.61 r78.74
  circle w10: c590.55,4724.41 r137.8
  circle w10: c2808.66,5439.01 r137.8
  circle w10: c2811.05,144.1 r137.79
  circle w10: c2165.35,4724.41 r137.8
  circle w10: c600.42,5713.98 r137.8
  circle w10: c604.33,3005.91 r137.8
  circle w10: c604.33,149.61 r137.8
  lines w5: 0,0 2856,0 2952.76,0 2952.76,5984.25 0,5984.25 0,0

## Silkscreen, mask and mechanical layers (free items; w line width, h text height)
Top Overlay:
  text "远程控制" at 394.76,5412.12 h150
  text "本地控制" at 1993.31,5408.12 h150
  text "开机" at 1719,4692 h150
  text "开机" at 152,4690 h150
  text "值机" at 851,4690 h150
  text "值机" at 2439,4690 h150
  text "电源" at 128.67,4085.57 h150
  text "值机" at 1800.41,4084.69 h150
  text "运行" at 128.78,3559.04 h150
  text "通讯" at 1819,3556 h150
  text "故障" at 128.78,2659.8 h150
  text "缺风" at 1745.77,2657.8 h150
  text "电热高温" at 1708,2152 h150
  text "初效" at 128.67,2147.59 h150
  text "中效" at 128.67,1627.51 h150
  text "预热高温" at 1707.42,1624.59 h150
  text "亚高" at 128.67,1115.31 h150
  text "防冻报警" at 1707.42,1112.78 h150
  text "高效" at 128.67,595.23 h150
  text "防冻停机" at 1711,591 h150
  text "A+B-V G" at 2615,577 h120 r90
  text "消防" at 1814,87 h150
  text "急停" at 128.67,80.66 h150
Bottom Overlay:
  text "CL-KB-V1.2" at 1404,3028 h120
  text "A+B-V G" at 2556,576 h120 r270
Mechanical 1:
  circle w10: c590.55,4724.41 r78.74
  circle w10: c2808.66,5439.01 r78.74
  circle w10: c2811.05,144.1 r78.74
  circle w10: c2165.35,4724.41 r78.74
  circle w10: c600.42,5713.98 r78.74
  circle w10: c604.33,3005.91 r78.74
  circle w10: c604.33,149.61 r78.74
  lines w5: 0,137.8 ccw(c137.8,137.8) 137.8,0 ; 0,5846.46 cw(c137.8,5846.46) 137.8,5984.25 ; 2814.96,0 ccw(c2814.96,137.8) 2952.76,137.8 ; 2814.96,5984.25 cw(c2814.96,5846.46) 2952.76,5846.46 ; 0,0 0,5984.25 2952.76,5984.25 2952.76,0 2856,0 0,0
Drill Drawing:
  text ".Legend" at 3138,93 h120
